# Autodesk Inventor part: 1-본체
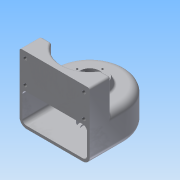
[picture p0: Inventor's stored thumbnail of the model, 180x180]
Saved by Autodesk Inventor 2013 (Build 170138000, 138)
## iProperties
Created: 2015-02
Part Number: 1-본체
Material: 알루미늄 6061
Document SubType Name: Modeling
Designer: Administrator
Density: 2.71 g/cm^3
Mass: 575.525 g
Surface Area: 708.306 cm^2
Volume: 212.371 cm^3
Author: Administrator
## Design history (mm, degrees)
sketch "스케치1"
  geometry: L1 (-50, 0)-(-50, -50); L2 (50, 0)-(50, -50); L3 (-50, -50)-(50, -50); A1 r 50 centre (0, 0) between (50, 0) and (-50, 0); 1 further point
  constraints: 6 end point, 2 parallel, 2 point on circle, 2 tangent, 1 centre point, 1 coincident, 1 perpendicular, 1 vertical
  dimensions: "d0" = 50 radius of A1; "d2" = 50 distance of L2.start L2.end
extrude "돌출1" new body sketch "스케치1" stored distance "d3" = 50; taper "d4" = 0 deg
sketch "스케치2"
  geometry: L1 (-50, 0)-(-50, -50) reference; L2 (-50, -50)-(50, -50) reference; L3 (50, -50)-(50, 0) reference; L4 (-50, -20)-(-50, -50); L5 (50, -20)-(50, -50); L6 (-50, -50)-(50, -50); L7 (-50, -20)-(-34.641, -20); L8 (34.641, -20)-(50, -20); A1 r 50 centre (0, 0) between (50, 0) and (-50, 0) reference; A2 r 40 centre (0, 0) between (-34.641, -20) and (34.641, -20)
  constraints: 10 end point, 3 perpendicular, 3 point on line, 2 point on circle, 1 centre point, 1 coincident, 1 collinear
  dimensions: "d5" = 40 radius of A2; "d7" = 30 distance of L4.start L1.end; "d8" = 30 distance of L5.start L5.end
extrude "돌출2" join sketch "스케치2" distance "d9" = 45; taper "d10" = 0 deg
node "작업 평면1"
sketch "스케치3"
  geometry: L1 (-50, 0)-(-50, -20) reference; L2 (50, -20)-(50, 0) reference; L3 (-50, -20)-(-50, -50) reference; L4 (50, -50)-(50, -20) reference; L5 (-46, -50)-(-46, -20); L6 (-46, -20)-(-46, 0); L7 (46, 0)-(46, -20); L8 (46, -20)-(46, -50); L9 (-46, -50)-(46, -50); L10 (-50, -50)-(50, -50) reference; A1 r 50 centre (0, 0) between (50, 0) and (-50, 0) reference; A2 r 46 centre (0, 0) between (46, 0) and (-46, 0); 1 further point
  constraints: 10 end point, 2 point on circle, 1 centre point, 1 collinear, 1 perpendicular, 4 other
  dimensions: "d12" = 4 radial gap between concentric circles of A1 A2
extrude "돌출3" cut sketch "스케치3" stored distance "d13" = 42; taper "d14" = 0 deg
sketch "스케치4"
  geometry: C1 r 25 at (0, 0); A1 r 50 centre (0, 0) between (50, 0) and (-50, 0) reference; A2 r 40 centre (0, 0) between (-34.641, -20) and (34.641, -20) reference
  constraints: 2 coincident, 1 centre point
  dimensions: "d15" = 50 diameter of C1
extrude "돌출4" join sketch "스케치4" distance "d17" = 10; taper "d18" = -20 deg
sketch "스케치5"
  geometry: C1 r 20 at (0, 0); A1 r 50 centre (0, 0) between (50, 0) and (-50, 0) reference
  constraints: 1 centre point, 1 coincident
  dimensions: "d19" = 40 diameter of C1
extrude "돌출5" join sketch "스케치5" distance "d21" = 9; taper "d22" = 0 deg
hole "구멍1" diameter "d25" = 20; stored, may be unused: countersink angle "d29" = 90 deg, drill point angle "d31" = 0 deg; dims "d23" = 10, "d24" = 10, "d26" = 6, "d27" = 28, "d28" = 10, "d30" = 14
sketch "스케치6"
  geometry: A1 r 46 centre (0, 0) between (46, 0) and (-46, 0) reference; 1 further point
  constraints: 1 coincident
hole "구멍2" sketch "스케치6" at (0, 0) diameter "d34" = 20; stored, may be unused: countersink angle "d38" = 90 deg, drill point angle "d40" = 0 deg; dims "d35" = 6, "d36" = 28, "d37" = 8, "d39" = 10
node "작업 평면2"
sketch "스케치7"
  geometry: L1 (-50, -25)-(50, -25) reference; 2 further points
  constraints: 1 coincident, 1 other
  dimensions: "d41" = 25 distance from line of point (0, 0) L1
feature "엠보싱1" sketch "스케치7" dims "d42" = 0.5, "d43" = 0
fillet "모깎기1" dims "d44" = 10, "d45" = 3
fillet "모깎기2" dims "d46" = 0.3, "d47" = 3, "d78" = 6
sketch "스케치8"
  geometry: C1 r 14 at (0, 0) reference; C2 r 21.36 at (0, 0) reference; A1 r 18 centre (0, 0) between (0, 18) and (-18, 0); 2 further points
  constraints: 4 point on circle, 2 horizontal alignment, 2 vertical alignment, 1 centre point, 1 coincident
  dimensions: "d48" = 36 diameter of A1
hole "구멍3" sketch "스케치8" at (0, 18), (-18, 0), (0, -18), (18, 0) diameter "d50" = 2.459; stored, may be unused: countersink angle "d54" = 90 deg, drill point angle "d56" = 118 deg; dims "d51" = 6, "d52" = 28, "d53" = 8, "d55" = 9
sketch "스케치11"
  geometry: L1 (97, -3)-(97, -85) reference; L2 (0, 0)-(94, 0) reference; L3 (88.75, -9)-(5.25, -9); L4 (5.25, -9)-(5.25, -42); L5 (5.25, -42)-(88.75, -42); L6 (88.75, -42)-(88.75, -9); 5 further points
  constraints: 8 end point, 4 coincident, 2 parallel, 1 horizontal, 1 perpendicular
  dimensions: "d66" = 33 distance of L5.end L3.start; "d68" = 83.5 distance of L3.start L3.end; "d69" = 9 distance between parallel lines of L2 L3; "d70" = 8.25 distance between parallel lines of L6 L1
hole "구멍4" sketch "스케치11" at (88.75, -9), (88.75, -42), (5.25, -9), (5.25, -42) diameter "d71" = 5.134; stored, may be unused: countersink angle "d75" = 90 deg, drill point angle "d77" = 118 deg; dims "d72" = 10, "d73" = 28, "d74" = 8, "d76" = 13
node "솔리드1"
other parameters: "d11" = 0
